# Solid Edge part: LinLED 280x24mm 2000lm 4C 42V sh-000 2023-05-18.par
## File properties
Author: jaroslaw.przewlocki
Template: iso metric part.par
Last saved by: jaroslaw.przewlocki
Revision: 1
Application: Solid Edge
Gęstość: 0,000 kg/m^3
Dokładność: 0,990
Username: jaroslaw.przewlocki
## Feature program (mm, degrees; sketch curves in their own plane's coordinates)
body "unnamed Body 1"
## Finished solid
Body 1: solid body, 1880 faces, 4836 edges, 3108 vertices.
  Faces by surface: plane 1293, cylinder 275, torus 128, cone 100, spline 52, sphere 32
  Edges by curve: line 3590, curve on surface 712, circle 330, ellipse 132, spline 72
Bounding box of the edges (mm; curved faces can reach further): 279.600 x 24.000 x 4.450, from (-139.8, -12, 0) to (139.8, 12, 4.45).
Cylindrical faces by radius (mm): R0.2 x92, R0.2169 x12, R0.25 x30, R0.3373 x12, R0.4 x16, R0.4006 x4, R0.4008 x4, R0.525 x4, R0.6 x40, R1 x20, R1.1 x8, R1.1989 x4, R1.199 x4, R1.2 x20, R2.15 x5
Conical faces (half-angle, radius in mm at the cone's reference point): 0.398 deg R1.1964 x4, 0.4493 deg R1.1964 x4, 0.4746 deg R1.1948 x4, 0.4758 deg R1.1948 x4, 0.5 deg R0.5056 x8, 0.5 deg R1.0082 x8, 1 deg R0.5511 x4, 10 deg R0.2132 x8, 10 deg R0.4132 x8, 16.0099 deg R1.1053 x4, 16.1249 deg R1.1279 x4, 18.8604 deg R1.0669 x8, 19.5041 deg R0.5138 x4, 19.8244 deg R0.5099 x4, 27.363 deg R0.6214 x4, 40.6434 deg R0.5161 x4, 43.3309 deg R0.4892 x4, 45 deg R0.575 x4, 45 deg R0.625 x8
Toroidal faces (ring radius, tube radius in mm): R0.0958 r0.3997 x8, R0.1076 r0.4 x4, R0.1101 r0.4001 x4, R0.1217 r0.4 x4, R0.1234 r0.4 x4, R0.1626 r0.228 x4, R0.1634 r0.2287 x4, R0.3287 r0.2001 x4, R0.3684 r0.2151 x4, R0.3703 r0.4 x4, R0.3818 r0.2 x8, R0.4166 r0.3983 x4, R0.5981 r0.197 x4, R0.5982 r0.197 x4, R0.6009 r0.3968 x4, R0.6009 r0.3969 x4, R0.6227 r0.2 x4, R0.6235 r0.2 x4, R0.8 r0.2 x8, R0.8522 r0.3 x4, R0.9002 r0.2 x4, R0.9018 r0.2 x4, R0.9197 r0.223 x4, R0.9365 r0.2 x4, R0.9663 r0.2263 x4, R0.9665 r0.2263 x4, R1.429 r1.2 x4, R1.8741 r0.2175 x4, R1.9007 r0.2 x4
Spherical faces by radius (mm): R0.2 x24, R0.6 x8
Planar faces by outward normal: +x 146, +y 148, +z 217, -x 146, -y 151, -z 17, oblique 468
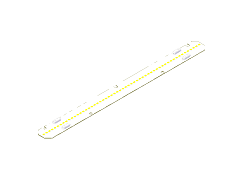
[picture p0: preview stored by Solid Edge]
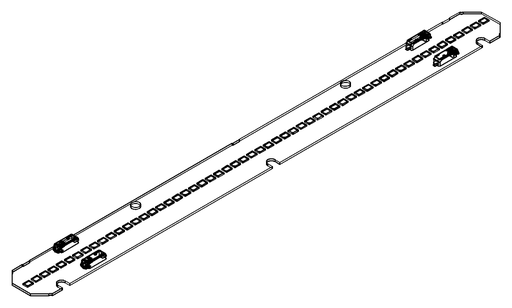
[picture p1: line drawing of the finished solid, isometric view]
